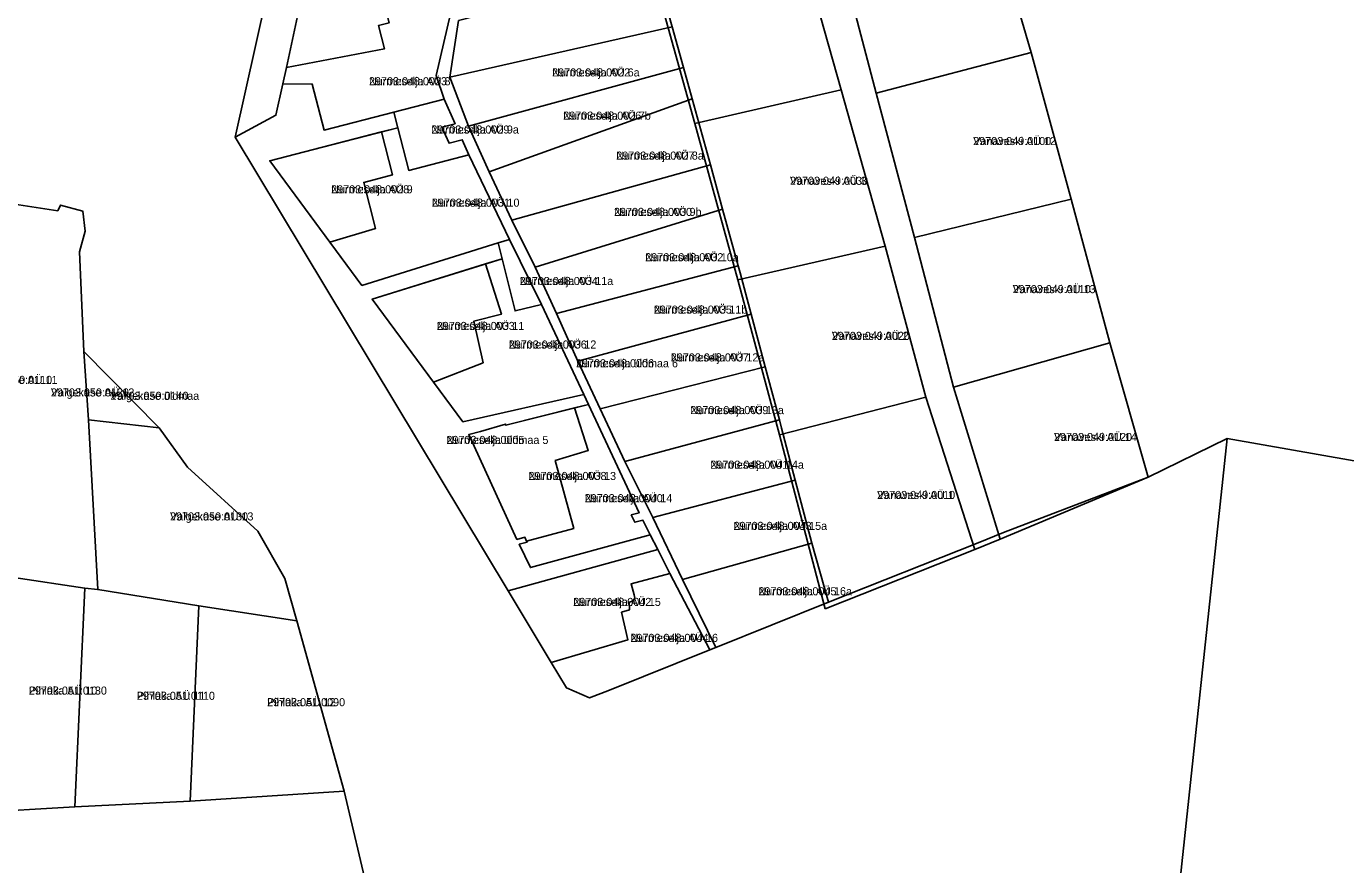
# Model space of a CAD drawing. Extents: x 504287 to 537970, y 6539941 to 6586214.
# Drawn here: x 520265.8 to 520511, y 6560569.2 to 6560725.1 of the extents above; entities that cross this region are included whole.
import ezdxf

# ---------------------------------------------------------------- set-up
doc = ezdxf.new("R2010")
doc.units = 0
for name, color, linetype in [('L_AADRESS', 7, 'Continuous'), ('PIIR', 7, 'Continuous'), ('TUNNUS', 7, 'Continuous')]:
    doc.layers.add(name, color=color, linetype=linetype)

msp = doc.modelspace()

# ---------------------------------------------------------------- linework, layer by layer
at = {"layer": 'PIIR'}
for points in [[(520393.39, 6560817.41), (520394.25, 6560829.05), (520387.32, 6560855.76), (520391.77, 6560857.58), (520394.38, 6560856.58), (520397.17, 6560851.16), (520408.91, 6560825.15), (520400.55, 6560822.16), (520399.14, 6560811.81), (520407.14, 6560777.78), (520415.14, 6560745.5), (520423.75, 6560712.68), (520430.87, 6560685.78), (520438.14, 6560657.98), (520446.79, 6560629.73), (520442.1, 6560627.8), (520432.98, 6560656.13), (520425.4, 6560684.17), (520417.22, 6560713.28), (520408.73, 6560743.38), (520400.25, 6560776.05), (520393.4, 6560803.05)], [(520472.98, 6560790.22), (520463.5, 6560827.64), (520513.23, 6560805.33), (520531.76, 6560798.85), (520572.54, 6560787.8), (520604.8, 6560777.28), (520681.07, 6560749.09), (520700, 6560739.6), (520709.62, 6560732.32), (520680.7, 6560715.22), (520623.92, 6560690.86), (520590.57, 6560668.31), (520554.21, 6560636.97), (520489, 6560648.42), (520474.34, 6560641.23), (520467.21, 6560666.19), (520460.01, 6560692.95), (520452.54, 6560720.21), (520446.02, 6560742.67), (520444.43, 6560748), (520428.02, 6560783.37)], [(520390.06, 6560706.99), (520379.38, 6560745.31), (520408.73, 6560743.38), (520417.22, 6560713.28)], [(520423.75, 6560712.68), (520415.14, 6560745.5), (520432.22, 6560743.39), (520432.45, 6560744.82), (520434.72, 6560745.06), (520435.31, 6560741.57), (520446.02, 6560742.67), (520452.54, 6560720.21)], [(520318.93, 6560714.34), (520313.46, 6560714.39), (520314.1, 6560717.42), (520332.34, 6560720.87), (520331.26, 6560725.25), (520333.21, 6560725.72), (520332.74, 6560727.68), (520335.7, 6560728.45), (520333.99, 6560735.66), (520336.46, 6560736.28), (520338.25, 6560729.1), (520345.45, 6560730.93), (520341.93, 6560715.94), (520343.43, 6560711.52), (520334.07, 6560709.1), (520321.11, 6560705.77)], [(520335.7, 6560728.45), (520332.74, 6560727.68), (520333.21, 6560725.72), (520331.26, 6560725.25), (520332.34, 6560720.87), (520314.1, 6560717.42), (520317.13, 6560731.4), (520333.99, 6560735.66)], [(520346.12, 6560726.18), (520382.88, 6560735.61), (520385.83, 6560724.99), (520344.5, 6560715.6)], [(520344.5, 6560715.6), (520385.83, 6560724.99), (520387.93, 6560717.44), (520347.96, 6560706.54)], [(520423.75, 6560712.68), (520452.54, 6560720.21), (520460.01, 6560692.95), (520430.87, 6560685.78)], [(520347.96, 6560706.54), (520387.93, 6560717.44), (520389.57, 6560711.57), (520351.83, 6560698)], [(520312.15, 6560708.54), (520313.46, 6560714.39), (520318.93, 6560714.34), (520321.11, 6560705.77), (520334.07, 6560709.1), (520334.82, 6560706.2), (520311.01, 6560700.07), (520328.16, 6560676.89), (520353.48, 6560684.79), (520354.2, 6560681.87), (520330.05, 6560674.34), (520346.93, 6560651.52), (520369.43, 6560656.63), (520370.25, 6560654.78), (520354.92, 6560650.9), (520354.86, 6560651.11), (520350.17, 6560649.7), (520348.02, 6560649.15), (520356.97, 6560629.67), (520358.44, 6560630.05), (520358.76, 6560629.36), (520358.87, 6560629.13), (520357.39, 6560628.75), (520359.47, 6560624.43), (520381.76, 6560630.51), (520383.14, 6560627.77), (520355.32, 6560620.09), (520304.57, 6560704.46)], [(520398.05, 6560677.94), (520390.06, 6560706.99), (520417.22, 6560713.28), (520425.4, 6560684.17)], [(520334.82, 6560706.2), (520334.07, 6560709.1), (520343.43, 6560711.52), (520345.47, 6560706.95), (520343.02, 6560706.3), (520344.34, 6560703.35), (520346.79, 6560703.99), (520348.02, 6560701.21), (520336.86, 6560698.27)], [(520351.83, 6560698), (520389.57, 6560711.57), (520390.49, 6560708.25), (520392.93, 6560699.33), (520356.04, 6560689.01)], [(520322.19, 6560684.96), (520330.68, 6560687.49), (520328.5, 6560696.05), (520333.85, 6560697.48), (520331.8, 6560705.43), (520334.82, 6560706.2), (520336.86, 6560698.27), (520348.02, 6560701.21), (520355.61, 6560685.45), (520353.48, 6560684.79), (520328.16, 6560676.89)], [(520331.8, 6560705.43), (520333.85, 6560697.48), (520328.5, 6560696.05), (520330.68, 6560687.49), (520322.19, 6560684.96), (520311.01, 6560700.07)], [(520356.04, 6560689.01), (520392.93, 6560699.33), (520395.2, 6560691.1), (520360.33, 6560680.32)], [(520263.11, 6560650.54), (520261.64, 6560654.9), (520263.59, 6560691.99), (520271.61, 6560690.76), (520272.14, 6560691.85), (520276.25, 6560690.73), (520276.73, 6560687), (520275.62, 6560683.17), (520276.47, 6560664.61), (520277.3, 6560651.87), (520279.05, 6560620.33), (520276.64, 6560620.62), (520263.46, 6560622.57)], [(520360.33, 6560680.32), (520395.2, 6560691.1), (520398.1, 6560680.51), (520364.33, 6560671.67)], [(520430.87, 6560685.78), (520460.01, 6560692.95), (520467.21, 6560666.19), (520438.14, 6560657.98)], [(520354.2, 6560681.87), (520353.48, 6560684.79), (520355.61, 6560685.45), (520361.51, 6560673.36), (520356.63, 6560672.14)], [(520405.75, 6560649.09), (520398.05, 6560677.94), (520425.4, 6560684.17), (520432.98, 6560656.13)], [(520341.47, 6560658.9), (520350.68, 6560662.53), (520348.94, 6560670.23), (520354.08, 6560671.52), (520351.15, 6560680.92), (520354.2, 6560681.87), (520356.63, 6560672.14), (520361.51, 6560673.36), (520369.43, 6560656.63), (520346.93, 6560651.52)], [(520351.15, 6560680.92), (520354.08, 6560671.52), (520348.94, 6560670.23), (520350.68, 6560662.53), (520341.47, 6560658.9), (520330.05, 6560674.34)], [(520364.33, 6560671.67), (520398.1, 6560680.51), (520398.45, 6560679.22), (520400.51, 6560671.56), (520368.31, 6560662.78)], [(520368.31, 6560662.78), (520400.51, 6560671.56), (520403.11, 6560661.77), (520372.47, 6560653.97)], [(520277.3, 6560651.87), (520276.47, 6560664.61), (520290.46, 6560650.39)], [(520438.14, 6560657.98), (520467.21, 6560666.19), (520474.34, 6560641.23), (520446.79, 6560629.73)], [(520372.47, 6560653.97), (520403.11, 6560661.77), (520405.76, 6560651.89), (520377.02, 6560644.16)], [(520357.39, 6560628.75), (520358.87, 6560629.13), (520358.76, 6560629.36), (520367.52, 6560631.67), (520364.08, 6560644.36), (520370.23, 6560646.17), (520367.64, 6560654.11), (520370.25, 6560654.78), (520379.69, 6560634.6), (520378.21, 6560634.21), (520378.9, 6560632.84), (520380.38, 6560633.24), (520381.76, 6560630.51), (520359.47, 6560624.43)], [(520414.26, 6560616.73), (520405.75, 6560649.09), (520432.98, 6560656.13), (520442.1, 6560627.8)], [(520277.3, 6560651.87), (520290.46, 6560650.39), (520295.73, 6560643.12), (520308.82, 6560631.18), (520313.81, 6560622.41), (520316.04, 6560614.51), (520297.83, 6560617.29), (520279.05, 6560620.33)], [(520350.17, 6560649.7), (520354.86, 6560651.11), (520354.92, 6560650.9), (520367.64, 6560654.11), (520370.23, 6560646.17), (520364.08, 6560644.36), (520367.52, 6560631.67), (520358.76, 6560629.36), (520358.44, 6560630.05), (520356.97, 6560629.67), (520348.02, 6560649.15)], [(520377.02, 6560644.16), (520405.76, 6560651.89), (520406.15, 6560650.37), (520408.7, 6560640.68), (520382.25, 6560633.73)], [(520470.87, 6560478), (520489, 6560648.42), (520554.21, 6560636.97), (520699.08, 6560611.61), (520702.52, 6560611), (520701.69, 6560605.93), (520720.27, 6560555.79), (520670.25, 6560540.81), (520572.24, 6560536.89), (520562.71, 6560475.36), (520495.12, 6560477.16), (520495.06, 6560478.36)], [(520382.25, 6560633.73), (520408.7, 6560640.68), (520411.78, 6560628.99), (520387.75, 6560622.18)], [(520383.14, 6560627.77), (520385.38, 6560623.34), (520378.2, 6560621.4), (520378.76, 6560619.33), (520378.88, 6560618.73), (520378.49, 6560618.16), (520377.82, 6560617.99), (520377.92, 6560616.58), (520376.41, 6560616.11), (520377.56, 6560610.97), (520363.31, 6560606.8), (520355.32, 6560620.09)], [(520387.75, 6560622.18), (520411.78, 6560628.99), (520414.9, 6560617.97), (520393.97, 6560609.56)], [(520257.91, 6560623.6), (520263.46, 6560622.57), (520276.64, 6560620.62), (520274.81, 6560579.95), (520255.84, 6560578.81)], [(520370.44, 6560600.22), (520366.18, 6560602.04), (520363.31, 6560606.8), (520377.56, 6560610.97), (520376.41, 6560616.11), (520377.92, 6560616.58), (520377.82, 6560617.99), (520378.49, 6560618.16), (520378.88, 6560618.73), (520378.76, 6560619.33), (520378.2, 6560621.4), (520385.38, 6560623.34), (520392.82, 6560609.1), (520374.2, 6560601.62)], [(520276.64, 6560620.62), (520279.05, 6560620.33), (520297.83, 6560617.29), (520296.22, 6560581), (520274.81, 6560579.95)], [(520297.83, 6560617.29), (520316.04, 6560614.51), (520324.82, 6560582.86), (520296.22, 6560581)], [(520116.2, 6560584.35), (520143.89, 6560583.03), (520172.86, 6560581.52), (520203.54, 6560580.07), (520236.32, 6560578.42), (520254.12, 6560578.76), (520255.84, 6560578.81), (520274.81, 6560579.95), (520296.22, 6560581), (520324.82, 6560582.86), (520329.36, 6560563.63), (520310.39, 6560562.71), (520295.35, 6560561.83), (520280.17, 6560560.87), (520265.21, 6560560.11), (520249.8, 6560559.14), (520244.74, 6560558.9), (520234.71, 6560559.27), (520219.94, 6560560.24), (520173.38, 6560562.51), (520162.65, 6560563.03), (520116.35, 6560565.44)]]:
    msp.add_lwpolyline(points, close=True, dxfattribs=at)
for points in [[(520345.85, 6560836.45), (520338.58, 6560815.5), (520337.38, 6560812.1), (520333.54, 6560801.52), (520330.42, 6560792.95), (520329.2, 6560787.29), (520328.48, 6560783.98), (520325.66, 6560770.91), (520323.65, 6560761.6), (520322.95, 6560758.34), (520319.72, 6560743.4), (520317.84, 6560734.71), (520317.13, 6560731.4), (520314.1, 6560717.42), (520313.46, 6560714.39), (520312.15, 6560708.54), (520304.57, 6560704.46), (520329.71, 6560817.12), (520338.67, 6560842.22)], [(520302.69, 6560839.49), (520329.71, 6560817.12), (520304.57, 6560704.46), (520355.32, 6560620.09), (520363.31, 6560606.8), (520366.18, 6560602.04), (520370.44, 6560600.22), (520374.2, 6560601.62), (520392.82, 6560609.1), (520393.97, 6560609.56), (520414.9, 6560617.97), (520442.74, 6560629.04), (520447.43, 6560630.97), (520474.34, 6560641.23), (520489, 6560648.42), (520470.87, 6560478)], [(520346.12, 6560726.18), (520344.5, 6560715.6), (520347.96, 6560706.54), (520351.83, 6560698), (520356.04, 6560689.01), (520360.33, 6560680.32), (520364.33, 6560671.67), (520368.31, 6560662.78), (520372.47, 6560653.97), (520377.02, 6560644.14), (520382.25, 6560633.73), (520387.75, 6560622.18), (520393.97, 6560609.56), (520392.82, 6560609.1), (520385.38, 6560623.34), (520383.14, 6560627.77), (520381.76, 6560630.51), (520380.38, 6560633.24), (520378.9, 6560632.84), (520378.21, 6560634.21), (520379.69, 6560634.6), (520370.25, 6560654.78), (520369.43, 6560656.63), (520361.51, 6560673.36), (520355.61, 6560685.45), (520348.02, 6560701.21), (520346.79, 6560703.99), (520344.34, 6560703.35), (520343.02, 6560706.3), (520345.47, 6560706.95), (520343.43, 6560711.52), (520341.93, 6560715.94), (520345.45, 6560730.93)], [(520329.36, 6560563.63), (520324.82, 6560582.86), (520316.04, 6560614.51), (520313.81, 6560622.41), (520308.82, 6560631.18), (520295.73, 6560643.12), (520290.46, 6560650.39), (520276.47, 6560664.61), (520275.62, 6560683.17), (520276.73, 6560687), (520276.25, 6560690.73), (520272.14, 6560691.85), (520271.61, 6560690.76), (520263.59, 6560691.99)]]:
    msp.add_lwpolyline(points, dxfattribs=at)

# ---------------------------------------------------------------- texts
at = {"layer": 'L_AADRESS'}
for s, p in [('Nurmeselja AÜ 8', (520329.46, 6560714.12)), ('Nurmeselja AÜ 6a', (520363.51, 6560715.76)), ('Nurmeselja AÜ 7b', (520365.57, 6560707.72)), ('Nurmeselja AÜ 9a', (520341.05, 6560705.14)), ('Vanaveski AÜ 12', (520441.79, 6560703)), ('Nurmeselja AÜ 8a', (520375.43, 6560700.29)), ('Vanaveski AÜ 3', (520407.73, 6560695.61)), ('Nurmeselja AÜ 9', (520322.43, 6560694.02)), ('Nurmeselja AÜ 10', (520341.16, 6560691.54)), ('Nurmeselja AÜ 9b', (520375.01, 6560689.82)), ('Nurmeselja AÜ 10a', (520380.82, 6560681.39)), ('Nurmeselja AÜ 11a', (520357.49, 6560676.97)), ('Vanaveski AÜ 13', (520449.14, 6560675.46)), ('Nurmeselja AÜ 11b', (520382.41, 6560671.65)), ('Nurmeselja AÜ 11', (520342.06, 6560668.61)), ('Nurmeselja AÜ 12', (520355.45, 6560665.16)), ('Vanaveski AÜ 2', (520415.51, 6560666.77)), ('Nurmeselja AÜ 12a', (520385.58, 6560662.76)), ('Nurmeselja üldmaa 6', (520367.95, 6560661.67)), ('Valgekase AÜ 11', (520256.06, 6560658.58)), ('Valgekase AÜ 12', (520270.34, 6560656.25)), ('Valgekase üldmaa', (520281.41, 6560655.62)), ('Nurmeselja AÜ 13a', (520389.2, 6560652.96)), ('Vanaveski AÜ 14', (520456.81, 6560647.96)), ('Nurmeselja üldmaa 5', (520343.86, 6560647.41)), ('Nurmeselja AÜ 14a', (520392.92, 6560642.81)), ('Nurmeselja AÜ 13', (520359.12, 6560640.71)), ('Nurmeselja AÜ 14', (520369.57, 6560636.58)), ('Vanaveski AÜ 1', (520423.93, 6560637.18)), ('Valgekase AÜ 13', (520292.48, 6560633.19)), ('Nurmeselja AÜ 15a', (520397.24, 6560631.43)), ('Nurmeselja AÜ 16a', (520401.86, 6560619.27)), ('Nurmeselja AÜ 15', (520367.44, 6560617.29)), ('Nurmeselja AÜ 16', (520378.07, 6560610.61)), ('Pihlaka AÜ 10', (520266.24, 6560600.8)), ('Pihlaka AÜ 11', (520286.32, 6560599.83)), ('Pihlaka AÜ 12', (520310.52, 6560598.64))]:
    msp.add_text(s, height=1.5, dxfattribs=at).set_placement(p)
at = {"layer": 'TUNNUS'}
for s, p in [('29703:048:0023', (520329.46, 6560714.12)), ('29703:048:0022', (520363.51, 6560715.76)), ('29703:048:0026', (520365.57, 6560707.72)), ('29703:048:0029', (520341.05, 6560705.14)), ('29703:049:0100', (520441.79, 6560703)), ('29703:048:0027', (520375.43, 6560700.29)), ('29703:049:0030', (520407.73, 6560695.61)), ('29703:048:0028', (520322.43, 6560694.02)), ('29703:048:0031', (520341.16, 6560691.54)), ('29703:048:0030', (520375.01, 6560689.82)), ('29703:048:0032', (520380.82, 6560681.39)), ('29703:048:0034', (520357.49, 6560676.97)), ('29703:049:0110', (520449.14, 6560675.46)), ('29703:048:0035', (520382.41, 6560671.65)), ('29703:048:0033', (520342.06, 6560668.61)), ('29703:048:0036', (520355.45, 6560665.16)), ('29703:049:0020', (520415.51, 6560666.77)), ('29703:048:0037', (520385.58, 6560662.76)), ('29703:048:0006', (520367.95, 6560661.67)), ('29703:050:0110', (520256.06, 6560658.58)), ('29703:050:0120', (520270.34, 6560656.25)), ('29703:050:0140', (520281.41, 6560655.62)), ('29703:048:0039', (520389.2, 6560652.96)), ('29703:049:0120', (520456.81, 6560647.96)), ('29703:048:0005', (520343.86, 6560647.41)), ('29703:048:0038', (520359.12, 6560640.71)), ('29703:048:0041', (520392.92, 6560642.81)), ('29703:048:0040', (520369.57, 6560636.58)), ('29703:049:0010', (520423.93, 6560637.18)), ('29703:050:0130', (520292.48, 6560633.19)), ('29703:048:0043', (520397.24, 6560631.43)), ('29703:048:0045', (520401.86, 6560619.27)), ('29703:048:0042', (520367.44, 6560617.29)), ('29703:048:0044', (520378.07, 6560610.61)), ('29703:051:0130', (520266.24, 6560600.8)), ('29703:051:0110', (520286.32, 6560599.83)), ('29703:051:0090', (520310.52, 6560598.64))]:
    msp.add_text(s, height=1.5, dxfattribs=at).set_placement(p)

doc.saveas('drawing.dxf')
